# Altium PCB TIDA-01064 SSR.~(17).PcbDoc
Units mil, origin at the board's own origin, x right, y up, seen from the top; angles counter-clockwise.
Board outline 4300 x 2000 mil, 2 copper layers (Top Layer, Bottom Layer), stack 62 mil thick; 74 components, 26 nets, 146 pads, 17 vias.
Unrouted connection lines stored in the file: 26.
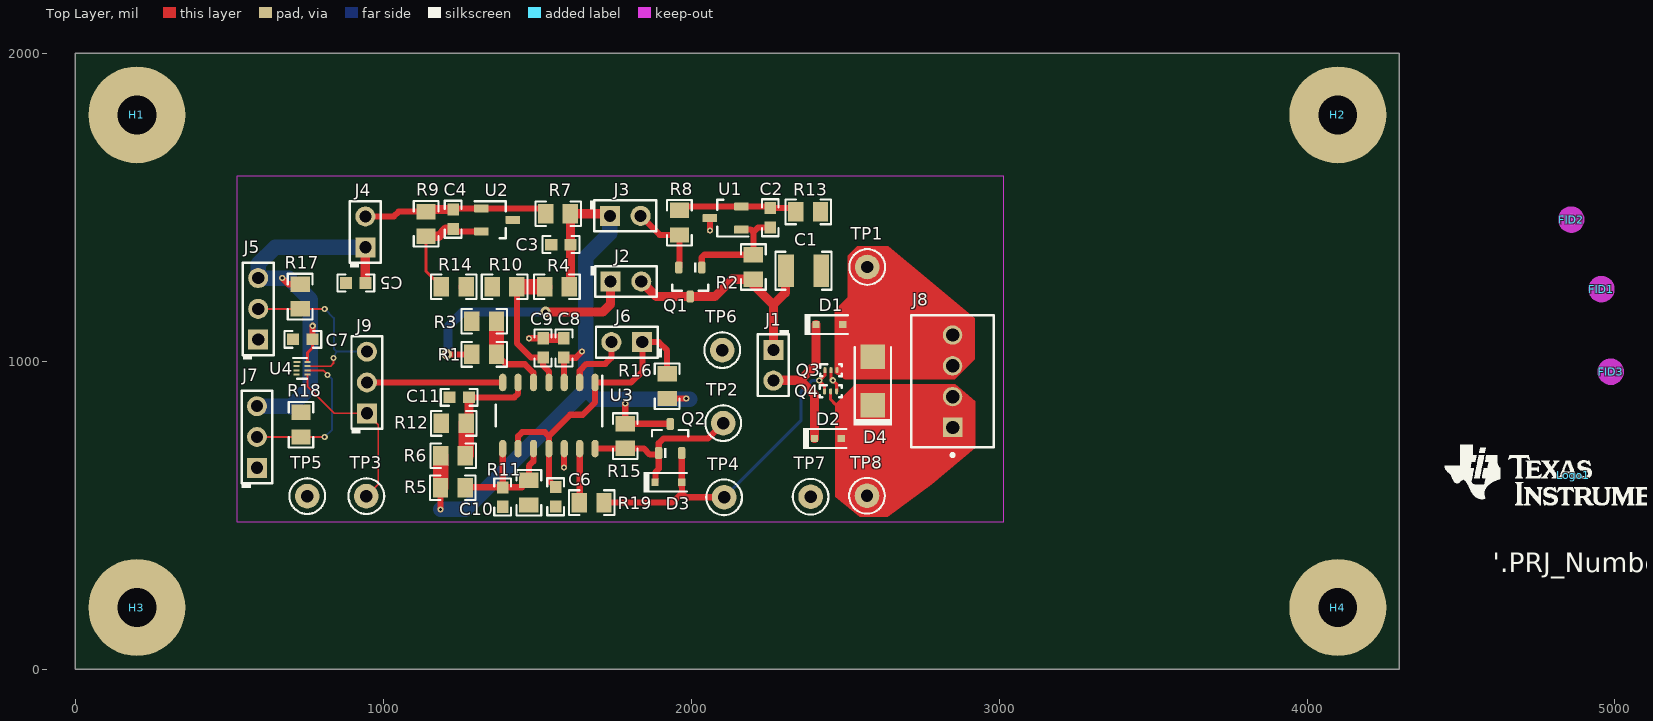
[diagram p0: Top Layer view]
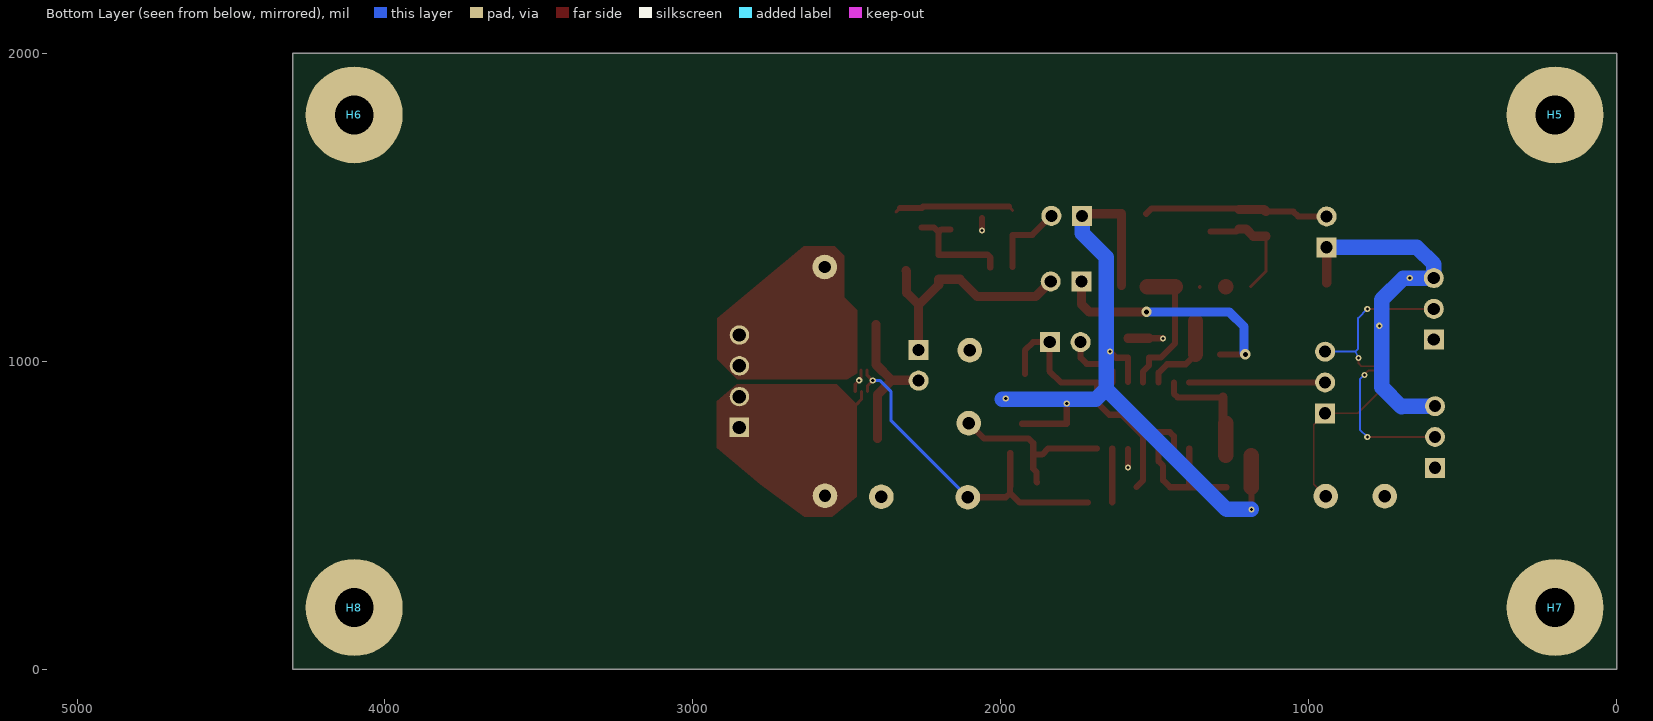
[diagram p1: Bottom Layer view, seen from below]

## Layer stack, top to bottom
Top Solder: solder mask 0.4, Solder Resist, Dk 3.5
Top Layer: signal copper 1.4
Dielectric1: core 59.2, FR-4, Dk 4.8
Bottom Layer: signal copper 1.4
Bottom Solder: solder mask 0.4, Solder Resist, Dk 3.5

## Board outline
0,0 4300,0 4300,2000 0,2000

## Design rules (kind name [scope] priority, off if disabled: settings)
AcuteAngle [All] p1: minimum=4.50000000000000E+0001 checktracksonly=FALSE
AssemblyTestPointUsage [All] p1: valid=2
Clearance Clearance_BoardEdge_MountingHoles [OnCopper and InComponentClass('Mounting Holes') vs IsKeepOut] p1: gap=25
Clearance Clearance_BoardEdge_Poly [OnCopper and InPoly vs IsKeepOut] p2: gap=25
Clearance Clearance_BoardEdge [OnCopper and Not InComponentClass('Logo') and not InComponentClass('FiducialMark') and not InRegion(1000,500,4000,800) and Not IsKeepout vs IsKeepOut] p3: gap=25
Clearance Clearance_Poly [InPolygon] p4: gap=15
Clearance [All] p5: gap=7
ComponentClearance ComponentClearance_Shunt [InComponentClass('Header') vs InComponentClass('Shunt')] p1: gap=0 collisioncheckmode=3 verticalgap=0 showdistances=FALSE
ComponentClearance ComponentClearance_Logo [InComponentClass('Logo')] p2: gap=50 collisioncheckmode=3 verticalgap=10 showdistances=FALSE
ComponentClearance ComponentClearance_ScrewToNut [(HasFootprint('NY PMS 440 0025 PH')) vs (HasFootprint('Keystone_1902C'))] p3: gap=5 collisioncheckmode=3 verticalgap=10 showdistances=FALSE
ComponentClearance ComponentClearance_MountingHoles [InComponentClass('Mounting Holes')] p4: gap=250 collisioncheckmode=3 verticalgap=100000 showdistances=FALSE
ComponentClearance ComponentClearance_SmallPassives [HasFootprint('0201*') or HasFootprint('0402*') or HasFootprint('0508') or HasFootprint('0603*') or HasFootprint('0612') or HasFootprint('0805*') or HasFootprint('0815*') or HasFootprint('0830*') or HasFootprint('1206*') or HasFootprint('1210*') or HasFootprint('1808*') or HasFootprint('1812*') or HasFootprint('1825*') or HasFootprint('2010*') or HasFootprint('2220*') or HasFootprint('2225*') or HasFootprint('2512*') or HasFootprint('2728*') or HasFootprint('3518*') vs HasFootprint('0201*') or HasFootprint('0402*') or HasFootprint('0508') or HasFootprint('0603*') or HasFootprint('0612') or HasFootprint('0805*') or HasFootprint('0815*') or HasFootprint('0830*') or HasFootprint('1206*') or HasFootprint('1210*') or HasFootprint('1808*') or HasFootprint('1812*') or HasFootprint('1825*') or HasFootprint('2010*') or HasFootprint('2220*') or HasFootprint('2225*') or HasFootprint('2512*') or HasFootprint('2728*') or HasFootprint('3518*')] p5: gap=15 collisioncheckmode=3 verticalgap=10 showdistances=FALSE
ComponentClearance ComponentClearance_THtoSMT [IsThruComponent vs IsSMTComponent] p6: gap=50 collisioncheckmode=3 verticalgap=30 showdistances=FALSE
ComponentClearance ComponentClearance_THtoTH [IsThruComponent vs IsThruComponent] p7: gap=50 collisioncheckmode=3 verticalgap=30 showdistances=FALSE
ComponentClearance [All] p8: gap=40 collisioncheckmode=3 verticalgap=10 showdistances=FALSE
DiffPairsRouting [All] p1: maxlimit=100 minlimit=10 mostfreqgap=10 toplayer_minwidth=15 toplayer_maxwidth=15 toplayer_prefwidth=15 bottomlayer_minwidth=15 bottomlayer_maxwidth=15 bottomlayer_prefwidth=15 maxuncoupledlength=1000
FabricationTestPointUsage TestPointUsage [All] p1: valid=2 allowmultiple=FALSE
FabricationTestpoint Testpoint [All] p1: side=3 testpointundercomponent=TRUE minsize=40 maxsize=100 preferedsize=60 minholesize=0 maxholesize=40 preferedholesize=32 testpointgrid=1 allowsidetop=TRUE allowsidebottom=TRUE usegrid=TRUE gridtolerance=0.01
FanoutControl Fanout_LCC [IsLCC] p1: bgadir=Out bgaviamode=Centered fanoutstyle=Auto fanoutdirection=Alternating viagrid=1 // Fanout_LCC (Default Rule)
FanoutControl Fanout_BGA [IsBGA] p2: bgadir=Out bgaviamode=Centered fanoutstyle=Auto fanoutdirection=Alternating viagrid=1 // Fanout_BGA (Default Rule)
FanoutControl Fanout_Default [All] p4: bgadir=Out bgaviamode=Centered fanoutstyle=Auto fanoutdirection=Alternating viagrid=1 // Fanout_Default (Default Rule)
FanoutControl Fanout_Small [(CompPinCount < 5)] p5: bgadir=Out bgaviamode=Centered fanoutstyle=Auto fanoutdirection=OutThenIn viagrid=1 // Fanout_Small (Default Rule)
HoleSize [All] p1: absolutevalues=TRUE maxlimit=251 minlimit=8 maxpercent=80.000 minpercent=20.000
MinimumAnnularRing MinimumAnnularRing_ThermalPadVias [IsVia and InAnyComponent] p1: minimumring=5.91
MinimumAnnularRing [All] p2: minimumring=9
MinimumSolderMaskSliver MinimumSolderMaskSliver_Logo [InComponentClass('Logo') vs InComponentClass('Logo')] p1: minsoldermaskwidth=0.7
MinimumSolderMaskSliver [All] p2: minsoldermaskwidth=3.94
PlaneClearance [All] p1: clearance=15
PlaneConnect [All] p1: planeconnectstyle=Direct reliefexpansion=10 reliefentries=4 reliefconductorwidth=10 reliefairgap=10
PolygonConnect [All] p1: connectstyle=Direct reliefconductorwidth=10 reliefentries=4 polygonreliefangle="90 Angle" airgapwidth=10
RoutingVias ThermalPadVias [IsVia and InAnyComponent] p1: holewidth=7.87 width=19.68 viastyle="Through Hole" minholewidth=7.87 minwidth=19.68 maxholewidth=12.99 maxwidth=23.62
RoutingVias [All] p2: holewidth=16 width=34 viastyle="Through Hole" minholewidth=7.87 minwidth=26 maxholewidth=40 maxwidth=65
SMDToCorner [All] p1: distance=30000
SilkToBoardRegionClearance [Not ((IsComment or IsDesignator) And (Hide <> 'False')) and not InRegion(1000,500,4000,800)] p1:
SilkToSilkClearance [All] p1: silktosilkclearance=0
SilkToSolderMaskClearance SilkscreenOverComponentPads [IsPad] p1: minsilkscreentomaskgap=0 clearancetoexposedcopper=TRUE
SolderMaskExpansion [All] p1: expansion=1.97
Width [All] p1: maxlimit=100 minlimit=6 preferedwidth=10 checkconnectedcopper=TRUE
14 further rules are at their usual default settings.

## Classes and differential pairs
component class "TIDA-01064 SSR_Relay": C1 C2 C3 C4 C6 C7 C8 C9 C10 C11 D1 D2 D3 D4 J1 J2 J3 J4 J5 J6 J7 J8 J9 Q1 Q2 Q3 Q4 R1 R2 R3 R4 R5 R6 R7 R8 R9 R10 R11 R12 R13 R14 R15 R16 R17 R18 R19 TP1 TP2 TP3 TP4 TP5 TP6 TP7 TP8 U1 U2 U3 U4
component class Header: J1 J2 J3 J4 J5 J6 J7 J9
component class "Mounting Holes": H1 H2 H3 H4
component class Logo: Logo1
component class "TIDA-01064 SSR_TID_Hardware": FID1 FID2 FID3 H1 H2 H3 H4 H5 H6 H7 H8 Logo1 ZZ1 ZZ2
component class FiducialMark: FID1 FID2 FID3
component class AssemblyNote: ZZ1 ZZ2

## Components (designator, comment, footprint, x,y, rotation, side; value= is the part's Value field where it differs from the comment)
C1 "C3225X7S2A335M200AB" 1210 2365,1294 r0 top
C2 "GRM1885C1H201JA01D" 0603 2257,1466 r90 top
C3 "GRM188R61E105KA12D" 0603 1577,1379 r180 top
C4 "GRM1885C1H201JA01D" 0603 1227,1461 r270 top
C5 "GRM188R61E105KA12D" 0603 911,1254 r180 top
C6 "GRM188R61E105KA12D" 0603 1560,560 r270 top
C7 "GRM188R71C104KA01D" 0603 739,1071 r0 top
C8 "GRM188R71C104KA01D" 0603 1587,1043 r270 top
C9 "GRM188R71C104KA01D" 0603 1519,1043 r270 top
C10 "GRM188R71C104KA01D" 0603 1388,559 r90 top
C11 "GRM188R71C104KA01D" 0603 1246.68,882.69 r0 top
D1 "1N4448WX-TP" sod-323 2449,1119 r0 top
D2 "1N4448WX-TP" sod-323 2444,749 r0 top
D3 "1N4448WX-TP" sod-323 1926,607 r0 top
D4 "SMAJ40CA" SMA 2590,936 r90 top
FID1 "Fiducial" Fiducial10-20 4956,1234 r0 top
FID2 "Fiducial" Fiducial10-20 4858,1460 r0 top
FID3 "Fiducial" Fiducial10-20 4986,966 r0 top
H1 "NY PMS 440 0025 PH" "NY PMS 440 0025 PH" 200,1800 r0 top locked
H2 "NY PMS 440 0025 PH" "NY PMS 440 0025 PH" 4100,1800 r0 top locked
H3 "NY PMS 440 0025 PH" "NY PMS 440 0025 PH" 200,200 r0 top locked
H4 "NY PMS 440 0025 PH" "NY PMS 440 0025 PH" 4100,200 r0 top locked
H5 "1902C" Keystone_1902C 200,1800 r180 bottom locked
H6 "1902C" Keystone_1902C 4100,1800 r180 bottom locked
H7 "1902C" Keystone_1902C 200,200 r180 bottom locked
H8 "1902C" Keystone_1902C 4100,200 r180 bottom locked
J1 "5-146278-2" TE_5-146278-2 2267,987 r270 top
J2 "5-146278-2" TE_5-146278-2 1788,1259 r0 top
J3 "5-146278-2" TE_5-146278-2 1786,1472 r0 top
J4 "5-146278-2" TE_5-146278-2 942,1420 r90 top
J5 "5-146278-3" TE_5-146278-3 594.02,1170 r90 top
J6 "5-146278-2" TE_5-146278-2 1791,1062 r180 top
J7 "5-146278-3" TE_5-146278-3 590.02,754 r90 top
J8 "282834-4" TEC_282834-4 2849,935 r90 top
J9 "5-146278-3" TE_5-146278-3 947,931 r90 top
Logo1 "Texas Instruments" TI_Stacked_Overlay_Small 4865,630 r0 top
Q1 "MMBTA05LT1G" SOT-23 1997,1257 r270 top
Q2 "MMBT3904LT1G" SOT-23 1932,749 r90 top
Q3 "CSD18541F5" YJK0003A 2454,971 r0 top
Q4 "CSD18541F5" YJK0003A 2453,902 r0 top
R1 "CRCW080510M0FKEA" 0805_HV 1327.71,1022 r0 top
R2 "CRCW0805205KFKEA" 0805_HV 2202,1306 r270 top
R3 "CRCW08053M09FKEA" 0805_HV 1328,1130 r0 top
R4 "CRCW080510M0FKEA" 0805_HV 1564,1242 r0 top
R5 "CRCW080510M0FKEA" 0805_HV 1226,589 r180 top
R6 "RC0805JR-0733ML" 0805_HV 1227,693 r180 top
R7 "CRCW0805100KFKEA" 0805_HV 1568,1479 r0 top
R8 "CRCW08053M74FKEA" 0805_HV 1962,1450 r270 top
R9 "CRCW0805806KFKEA" 0805_HV 1139,1446 r90 top
R10 "CRCW08057M50FKEA" 0805_HV 1394,1242 r0 top
R11 "CRCW08054M32FKEA" 0805_HV 1473,573 r90 top
R12 "CRCW08056M49FKEA" 0805_HV 1229,798 r0 top
R13 "CRCW08051M30FKEA" 0805_HV 2380,1485 r180 top
R14 "CRCW08052M80FKEA" 0805_HV 1229,1242 r180 top
R15 "CRCW080590K9FKEA" 0805_HV 1786,757 r90 top
R16 "CRCW08051M82FKEA" 0805_HV 1922,919 r270 top
R17 "CRCW0805124KFKEA" 0805_HV 730,1210 r90 top
R18 "CRCW0805124KFKEA" 0805_HV 733,794 r90 top
R19 "CRCW08050000Z0EA" 0805_HV 1677,541 r0 top
TP1 "5001" Keystone5001 2572,1306 r0 top
TP2 "5001" Keystone5001 2104,799 r0 top
TP3 "5001" Keystone5001 945.18,561.88 r0 top
TP4 "5001" Keystone5001 2107,558 r0 top
TP5 "5001" Keystone5001 753.18,561.88 r0 top
TP6 "5001" Keystone5001 2101,1036 r0 top
TP7 "5001" Keystone5001 2388,560 r0 top
TP8 "5001" Keystone5001 2571,563 r0 top
U1 "ATL431AIDBZR" DBZ0003A_M 2112,1465 r180 top
U2 "ATL431AIDBZR" DBZ0003A_M 1370,1459 r0 top
U3 "LP339D" D0014A_N 1538,823.68 r270 top
U4 "SN74AUP1G74DQER" DQE0008A 736,977 r0 top
ZZ1 "These assemblies are ESD sensitive, ESD precautions shall be observed." AssemblyNote 185,3829.11 r0 top
ZZ2 "These assemblies must be clean and free from flux and all contaminants. Use of no clean flux is not acceptable." AssemblyNote 185,3740.56 r0 top
ZZ3 "These assemblies must comply with workmanship standards IPC-A-610 Class 2, unless otherwise specified." AssemblyNote 185,3652 r0 top

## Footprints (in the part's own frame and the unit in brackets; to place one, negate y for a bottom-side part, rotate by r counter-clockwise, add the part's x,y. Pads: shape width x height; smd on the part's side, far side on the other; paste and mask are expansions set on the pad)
0603 [mm] "0603 from SM-752 data"
  rect 1x0.95 smd: 1(-0.8,0) 2(0.8,0)
  silkscreen extent -1.52,-0.69 1.52,0.69, body extent -0.87,-0.47 0.87,0.47, height 1
0805_HV [mil] "0805 with 30mil clearance between pads"
  rect 50x63 smd: 1(-40,0) 2(40,0)
  silkscreen extent -74,-40 74,40, body extent -43,-29 43,29, height 57
1210 [mm] "1210 from SM-752 data"
  rect 1.3x2.7 smd: 1(-1.45,0) 2(1.45,0)
  silkscreen extent -2.32,-1.57 2.32,1.57, body extent -1.7,-1.35 1.7,1.35, height 1.35
AssemblyNote [mil] "Assembly Note"
D0014A_N [mm] "SOIC, 14-Leads, Body 8.7x3.9mm, Pitch 1.27mm, IPC Medium Density"
  oval 1.45x0.6 smd: 1(-2.725,3.81) 2(-2.725,2.54) 3(-2.725,1.27) 4(-2.725,0) 5(-2.725,-1.27) 6(-2.725,-2.54) 7(-2.725,-3.81) 8(2.725,-3.81) 9(2.725,-2.54) 10(2.725,-1.27) 11(2.725,0) 12(2.725,1.27) 13(2.725,2.54) 14(2.725,3.81)
  silkscreen extent -3.3,-4.4 0.9,4.4, body extent -3.02,-4.32 3.02,4.32, height 1.6
DBZ0003A_M [mm] "SOT23, 3-Leads, Body 2.9x1.3mm, Pitch 0.95mm, Lead Span 2.4mm, IPC Low Density"
  rrect15% 1.2x0.65 smd: 1(-1.3,0.95) 2(-1.3,-0.95) 3(1.3,0)
  silkscreen extent -1.85,-1.5 0.7,1.53, body extent -1.26,-1.46 1.26,1.46, height 0.98
DQE0008A [mm] "SON, 8-Leads, Body 1.4x1mm, Pitch 0.35mm, TI Recommended"
  rect 0.6x0.16 smd mask+0: 1(-0.4,0.525)
  rect 0.5x0.16 smd mask+0: 2(-0.45,0.175) 3(-0.45,-0.175) 4(-0.45,-0.525) 5(0.45,-0.525) 6(0.45,-0.175) 7(0.45,0.175) 8(0.45,0.525)
  silkscreen extent -0.7,-0.85 0.4,0.85, body extent -0.53,-0.72 0.53,0.73, height 0.41
Fiducial10-20 [mm]
  round 1 smd mask+0.5: 1(0,0)
  Top Layer keep-out circle w1.178: c0,0 r0.5
Keystone5001 [mil] "For Keystone 500x miniature loop terminals"
  round 80 hole 40: 1(0,0)
  silkscreen extent -58,-58 58,58, body extent -49,-49 49,49, height 182
Keystone_1902C [mil] "Hex Standoff, 4-40 threaded, nylon"
  body extent -145,-126 146,126, height 501
"NY PMS 440 0025 PH" [mm] "4-40 nylon screw and mounting hole"
  round 8 hole 3.2: 1(0,0)
  body extent -3.3,-3.3 3.3,3.3, height 2.69
SMA [mm] "Molded Diode, 2-Leads, Body 4.3x2.6mm, IPC Medium Density, based on OnSemi component dimensions and land pattern"
  rect 2x2 smd: 1(-2,0) 2(2,0)
  silkscreen extent -3.66,-1.57 2.79,1.57, body extent -2.6,-1.3 2.6,1.3, height 2.42
sod-323 [mm] "NXP recommended land pattern"
  rect 0.6x0.6 smd paste-0.05: 1(-1.1,0) 2(1.1,0)
  silkscreen extent -2.06,-0.86 1.53,0.86, body extent -1.3,-0.67 1.3,0.68, height 1.1
SOT-23 [mm] "SOT23, 3-Leads, Body 2.9x1.3mm, Pitch 0.95mm, Lead Span 2.5mm, IPC Medium Density"
  rrect50% 1x0.6 smd: 1(-1.2,0.95) 2(-1.2,-0.95) 3(1.2,0)
  silkscreen extent -1.63,-1.5 0.7,1.5, body extent -1.16,-1.45 1.21,1.45, height 1
TE_5-146278-2 [mm] "TE CONNECTIVITY"
  rect 1.65x1.65 hole 1: 1(-1.27,0)
  round 1.65 hole 1: 2(1.27,0)
  silkscreen extent -2.92,-1.27 2.54,1.27, body extent -2.41,-1.17 2.41,1.17, height 8.13
TE_5-146278-3 [mm] "TE CONNECTIVITY"
  rect 1.65x1.65 hole 1: 1(-2.54,0)
  round 1.65 hole 1: 2(0,0) 3(2.54,0)
  silkscreen extent -4.19,-1.27 3.81,1.27, body extent -3.68,-1.17 3.68,1.17, height 8.13
TEC_282834-4 [mm] "TEC"
  rect 1.6x1.6 hole 1.1: 1(-3.81,0)
  round 1.6 hole 1.1: 2(-1.27,0) 3(1.27,0) 4(3.81,0)
  silkscreen extent -6.2,-3.4 5.44,3.4, body extent -5.31,-3.25 5.31,3.25, height 10.02
TI_Stacked_Overlay_Small [mil]
  silkscreen extent -418,-98 418,98
YJK0003A [mm] "SMD, 3-Leads, Body 1.49x0.73mm"
  rrect80% 0.25x0.49 smd paste-0.05 mask-0.05: 1(-0.5,0) 2(0,0) 3(0.5,0)
  silkscreen extent -0.9,-0.5 0.9,0.5, body extent -0.75,-0.37 0.74,0.36, height 0.35

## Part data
C1: "CAP, CERM, 3.3 µF, 100 V, +/- 20%, X7S, 1210"
C2 C4: "CAP, CERM, 200 pF, 50 V, +/- 5%, C0G/NP0, 0603"
C3 C5 C6: "CAP, CERM, 1 µF, 25 V, +/- 10%, X5R, 0603"
C7 C8 C9 C10 C11: "CAP, CERM, 0.1 µF, 16 V, +/- 10%, X7R, 0603"
D1 D2 D3: "Diode, Switching, 75 V, 0.25 A, SOD-323"
D4: "Diode, TVS, Bi, 40 V, 400 W, SMA"
FID1 FID2 FID3: "Fiducial mark.  There is nothing to buy or mount."
H1 H2 H3 H4: "Machine Screw, Round, #4-40 x 1/4, Nylon, Philips panhead"
H5 H6 H7 H8: "Standoff, Hex, 0.5\"L #4-40 Nylon"
J1 J2 J3 J4 J6: "Header, 100mil, 2x1, Tin, TH"
J5 J7 J9: "Header, 100mil, 3x1, Tin, TH"
J8: "Terminal Block, 100mil, 4X1 TH"
Logo1: library part TI_Logo, "Texas Instrument Corporate Signature"
Q1: library part "MMBTA05LT1G, ON Semiconductor", "Transistor, NPN, 60 V, 0.5 A, AEC-Q101, SOT-23"
Q2: library part "MMBT3904LT1G, ON Semiconductor", "Transistor, NPN, 40 V, 0.2 A, SOT-23"
Q3 Q4: "MOSFET, N-CH, 60 V,  A, PICOSTAR-3"
R1 R4 R5: "RES, 10.0 M, 1%, 0.125 W, 0805"
R2: "RES, 205 k, 1%, 0.125 W, 0805"
R3: "RES, 3.09 M, 1%, 0.125 W, 0805"
R6: "RES, 33 M, 5%, 0.125 W, 0805"
R7: "RES, 100 k, 1%, 0.125 W, 0805"
R8: "RES, 3.74 M, 1%, 0.125 W, 0805"
R9: "RES, 806 k, 1%, 0.125 W, 0805"
R10: "RES, 7.50 M, 1%, 0.125 W, 0805"
R11: "RES, 4.32 M, 1%, 0.125 W, 0805"
R12: "RES, 6.49 M, 1%, 0.125 W, 0805"
R13: "RES, 1.30 M, 1%, 0.125 W, 0805"
R14: "RES, 2.80 M, 1%, 0.125 W, 0805"
R15: "RES, 90.9 k, 1%, 0.125 W, 0805"
R16: "RES, 1.82 M, 1%, 0.125 W, 0805"
R17 R18: "RES, 124 k, 1%, 0.125 W, 0805"
R19: "RES, 0, 5%, 0.125 W, 0805"
TP1 TP2 TP3 TP4 TP5 TP6 TP7 TP8: "Test Point, Miniature, Black, TH"
U1 U2: "2.5V Low Iq Adjustable Precision Shunt Regulator, DBZ0003A"
U3: "Quad, Low-Power, General Purpose Differential Comparator, D0014A"
U4: "LOW-POWER SINGLE POSITIVE-EDGE-TRIGGERED D-TYPE FLIP-FLOP WITH CLEAR AND PRESET, DQE0008A"
ZZ1 ZZ2 ZZ3: library part AssemblyNote

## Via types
v1: diameter 20, hole 10, Top Layer to Bottom Layer, 15 vias
v2: diameter 34, hole 16, Top Layer to Bottom Layer, 2 vias

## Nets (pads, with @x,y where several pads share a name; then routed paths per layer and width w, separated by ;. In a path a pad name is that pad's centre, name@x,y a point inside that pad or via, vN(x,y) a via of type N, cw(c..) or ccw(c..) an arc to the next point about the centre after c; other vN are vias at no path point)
3.3V: C5.1 C7.2 J4.1 J5.3 J7.3 R17.2 R18.2 U4.8 | length 1404.1
  Top Layer w10: U4.8@753.72,1000.04 753.72,1026.52 770.5,1043.3 C7.2
  Top Layer w20: v1(672,1270) 692,1250 R17.2 ; C7.2 770.5,1114.5 v1(771,1115)
  Top Layer w30: J4.1 942,1254.5 C5.1
  Bottom Layer w50: J7.3@591.02,853 J7.3 697,854 699,852 763,916 763,1200 693,1270 v1(672,1270) J5.3 594.02,1314.98 649.04,1370 J4.1
10V: C3.1 C8.2 J3.1 Q2.3 R4.2 R5.2 R6.2 R7.2 R15.2 R16.2 U3.3 | length 2545.4
  Top Layer w10: R5.2 R5.2@1187,590 ; U3.3@1587,931.97 U3.3 ; R4.2 R4.2@1608.5,1246.5 ; C3.1@1608,1379.5 C3.1 ; J3.1@1729,1479 J3.1
  Top Layer w20: v1(1186,519) R5.2 ; U3.3@1587,931.97 C8.2 1625.5,1011.5 v1(1646,1032) ; v1(1786,863) R15.2 Q2.3@1931.24,797 ; R16.2 v1(1984,879)
  Top Layer w30: C3.1@1608,1379.5 R7.2 J3.1@1729,1479 ; R4.2@1608.5,1246.5 C3.1
  Top Layer w50: R5.2@1187,590 R6.2
  Bottom Layer w50: v1(1186,519) 1267,519 1658,910 ; J3.1 1736,1416 1658,1338 1658,910 ; 1995,876 1692,876 1658,910
GND: C1.2 C3.2 C5.2 C6.2 C7.1 C8.1 C9.1 C10.1 C11.1 J5.1 J7.1 Q3.2 Q4.3 R3.1 R10.1 R11.1 R12.1 R13.1 R14.1 TP5.1 TP6.1 TP7.1 U1.3 U2.3 U3.12 U4.1 U4.2 U4.4 | length 296.8
  Top Layer w10: R10.1@1354,1239 R10.1 ; v1(1587,655) v1@1588,656 ; Q3.2 2454,944 v1(2460,938) 2472.69,925.31 Q4.3
  Top Layer w20: v1(1473,1074) 1473.5,1074.5 C9.1 ; v1(1587,655) U3.12@1587,715.4 ; U1.3 2060.82,1424.18 v1(2061,1424)
  Top Layer w30: C9.1 C8.1
HV1: D1.2 D4.2 J8.3 J8.4 Q3.3 TP1.1 | length 0.4
  Top Layer w20: D4.2@2589.74,1015 D4.2
HV2: D2.2 D4.1 J8.1 J8.2 Q4.2 TP8.1 | length 49.2
  Top Layer w10: Q4.2 2453,875.75 2468,860.75
  Top Layer w20: D4.1@2588.74,856 D4.1
NetC1_1: C1.1 J1.1 J2.2 Q1.3 R2.2 | length 791.6
  Top Layer w30: J2.2 1887.24,1209.76 Q1.3 2076.76,1209.76 2133,1266 R2.2 2202,1248 2267,1183 ; J1.1 2267,1183 ; C1.1 2306,1292.09 2306,1222 2267,1183
NetC2_1: C2.1 Q1.1 R2.1 U1.1 | length 381.8
  Top Layer w10: 2034,1337 2034.4,1336.6 ; 2192.6,1427.6 2193,1428
  Top Layer w20: 2034,1337 2043,1346 R2.1 2202,1419 ; Q1.1 2034.4,1336.6 ; U1.1 2192.6,1427.6 ; 2193,1428 2202,1419 ; C2.1 2217.5,1434.5 2202,1419
NetC2_2: C2.2 R8.1 R13.2 U1.2 | length 390.3
  Top Layer w10: R8.1 R8.1@1974.4,1502.4 ; C2.2@2252.09,1502.4 C2.2 ; R13.2@2327.5,1497.5 R13.2
  Top Layer w20: R8.1@1974.4,1502.4 U1.2 C2.2@2252.09,1502.4 ; C2.2 R13.2@2327.5,1497.5
NetC4_1: C4.1 J4.2 R7.1 R9.2 U2.1 | length 609.5
  Top Layer w10: U2.1@1314.91,1492.5 U2.1
  Top Layer w20: J4.2 1034,1470 1050,1486 R9.2 ; C4.1 1230.5,1496 U2.1 1510.6,1496.4 R7.1
  Top Layer w30: R9.2 1145.5,1492.5 C4.1
NetC4_2: C4.2 R9.1 R14.2 U2.2 | length 377.5
  Top Layer w10: R9.1 1139,1292 R14.2
  Top Layer w20: C4.2 1234.91,1421.6 U2.2
  Top Layer w30: R9.1 1180,1406 1203.5,1429.5 C4.2
NetC6_1: C6.1 J6.1 R16.1 U3.1 U3.9 U3.11 | length 1018
  Top Layer w10: J6.1 J6.1@1842,1061
  Top Layer w20: U3.9 1438,757 1451,770 1525,770 1538,757 ; C6.1 1538,613.5 U3.11 1538,757 ; J6.1 1895,1062 1922,1035 R16.1 ; J6.1@1842,1061 1842,968 1804.97,930.97 U3.1 1688,866 1648,826 1607,826 1538,757
NetD1_1: D1.1 D2.1 J1.2 | length 498.2
  Top Layer w30: J1.2 2268,938 2354,938 ; D2.1 2400.69,891.31 2354,938 ; D1.1 2405.69,1053.75 2405.39,1053.45 2405.39,989.39 2354,938
NetD3_1: D3.1 Q2.1 R15.1 TP2.1 U3.14 | length 583.1
  Top Layer w10: R15.1@1785.4,716.4 R15.1
  Top Layer w20: U3.14 R15.1@1785.4,716.4 ; R15.1 1846,717 1866,697 Q2.1@1894.35,697 ; D3.1 1884,608.31 1884,640 1894.6,650.6 1894.6,696.76 Q2.1@1894.35,697 ; TP2.1 2054,749 1910,749 1895,734 1895,697.65 Q2.1@1894.35,697
NetD3_2: D3.2 Q2.2 Q3.1 Q4.1 R19.2 TP4.1 | length 1143.8
  Top Layer w10: Q4.1 2433.32,919.68 v1(2416,937) 2417,937 2434.32,954.32 Q3.1
  Top Layer w20: R19.2 1939,541 1970,572 ; Q2.2 1969.4,607.09 D3.2 1970,572 ; TP4.1 1984,558 1970,572
  Bottom Layer w10: TP4.1 2357,808 2357,902 2392,937 v1(2416,937)
NetJ2_1: J2.1 R1.1 | length 805.6
  Top Layer w20: v2(1206,1022) R1.1
  Top Layer w30: v2(1527,1160) 1713,1160 1738,1185 J2.1
  Bottom Layer w30: v2(1206,1022) 1210,1026 1210,1112 1258,1160 v2(1527,1160)
NetJ3_2: J3.2 Q1.2 R8.2 | length 258.4
  Top Layer w10: Q1.2 Q1.2@1962,1306.65
  Top Layer w20: J3.2 1898,1410 R8.2 Q1.2@1962,1306.65
NetJ6_2: J6.2 U3.2 | length 209.4
  Top Layer w20: U3.2 1638,969 1660,991 1721,991 1741,1011 J6.2
NetJ9_1: J9.1 TP3.1 U4.5 | length 568
  Top Layer w6: U4.5 753.72,918.28 841,831 J9.1 984,794 984,600.71 TP3.1
NetJ9_2: J9.2 U3.7 | length 441
  Top Layer w20: J9.2 U3.7
NetR19_1: R19.1 U3.13 | length 177.2
  Top Layer w10: R19.1 R19.1@1638,542 ; U3.13@1637,715.4 U3.13
  Top Layer w20: R19.1@1638,542 U3.13
OFF#: J7.2 R18.1 U4.6 | length 509.3
  Top Layer w6: J7.2 R18.1 v1(810,754) ; U4.6 804.89,970.11 v1(819.5,955.5)
  Bottom Layer w6: v1(810,754) 834,778 834,941 v1(819.5,955.5)
ON#: J5.2 J9.3 R17.1 U4.7 | length 598
  Top Layer w6: J5.2 R17.1 v1(810,1170) ; U4.7 828.89,983.89 838,993 v1(838,1011)
  Bottom Layer w6: v1(810,1170) 840,1140 840,1040 849,1031 ; v1(838,1011) 849,1031 ; J9.3 849,1031
VREF1: C9.2 R4.1 R10.2 U3.4 | length 466.7
  Top Layer w10: C9.2@1518.5,1012 C9.2
  Top Layer w20: R10.2 1434,1058 1480,1012 C9.2@1518.5,1012 ; C9.2 1519,986 1538,967 U3.4
  Top Layer w50: R10.2 R4.1
VREF2: C10.2 R5.1 R11.2 U3.8 U3.10 | length 454.5
  Top Layer w10: R5.1 R5.1@1267.5,590.5 ; U3.8 U3.8@1389.45,714.95
  Top Layer w20: R5.1@1267.5,590.5 C10.2 ; U3.8 C10.2 ; U3.10 1488,675 1473,660 R11.2 1450.5,590.5 C10.2
VREF3: C11.2 R6.1 R12.2 U3.6 | length 395.2
  Top Layer w10: R6.1 R6.1@1269,695 ; R12.2 R12.2@1278.18,807.18
  Top Layer w20: C11.2 1425.69,882.69 1438,895 U3.6
  Top Layer w30: R12.2@1278.18,807.18 C11.2
  Top Layer w50: R6.1@1269,695 R12.2
VUVLO: R1.2 R3.2 U3.5 | length 284.7
  Top Layer w10: R3.2@1367.71,1129.71 R3.2 ; 1487.26,962.74 1488,962.74
  Top Layer w20: R1.2 1399.71,990 1460,990 1487.26,962.74 ; U3.5 1488,962.74
  Top Layer w50: R1.2 R3.2@1367.71,1129.71
pads on no net: FID1.1 FID2.1 FID3.1 H1.1 H2.1 H3.1 H4.1 U4.3

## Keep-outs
Top Layer:
  rectangle net GND: 525,478 3015,1600
Keep-Out Layer:
  text ".Layer_Name" at 577,-858.49 h60

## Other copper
Top Layer:
  region net HV1: 2546,942 2499,942 2466.5,961 2466.5,1007 2466.5,1166 2508.75,1208.25 2508.75,1343 2539.25,1373.5 2640,1373.5 2775,1261 2921.5,1138.92 2921.5,1007 2856.5,942 2697,942
  region net HV2: 2547.5,494.25 2468,559.25 2468,860.75 2533,925.75 2858,925.75 2923,869.75 2923,718.75 2781,601 2639,494.25
  text ".Layer_Name" at 577,-858.49 h60
Bottom Layer:
  text ".Layer_Name" at 577,-858.49 h60

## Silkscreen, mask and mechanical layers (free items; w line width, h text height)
Top Overlay:
  text "'.PRJ_Number' .PCB_Rev" at 4603,294 h108.27
  text ".Layer_Name" at 577,-858.49 h60
Bottom Overlay:
  text ".Layer_Name" at 577,-858.49 h60
Top Paste:
  text ".Layer_Name" at 577,-858.49 h60
Bottom Paste:
  text ".Layer_Name" at 577,-858.49 h60
Top Solder:
  text ".Layer_Name" at 577,-858.49 h60
  text ".Layer_Name" at 577,-858.49 h60
Bottom Solder:
  text ".Layer_Name" at 577,-858.49 h60
Drill Guide:
  text ".Layer_Name" at 577,-858.49 h60
M1 Board Outline:
  the board outline again, w10
  text ".Layer_Name" at 577,-858.49 h60
M2 Board Dimensions:
  rectangle: 0,-275 125,-150
  rectangle: 125,-400 500,-275
  lines w7: 0,-275 1000,-275 ; 125,-400 125,-150 ; 250,-400 250,-150 ; 500,-400 500,-150 ; 750,-400 750,-150 ; 0,-400 1000,-400 1000,-150 0,-150 0,-400
  text ".Layer_Name" at 577,-858.49 h60
M3 3D STEP Top:
  text ".Layer_Name" at 577,-858.49 h60
M4 3D STEP Bottom:
  text ".Layer_Name" at 577,-858.49 h60
M5 Assembly Top:
  lines w10: -292,-930.17 6308,-930.17 ; -292,-726.83 6310,-726.83 ; -292,-523.5 -292,-1133.5 3713,-1133.5 6310,-1133.5 6310,-523.5 -291.5,-523.5 -291.5,-1133.5 1284,-1133.5 ; 2173,-1133.5 2173,-523.5 ; 3440,-726.83 3440,-523.5 ; 4280,-726.83 4280,-523.5 ; 4902,-1140 4902,-937.17
  text "COMPONENTS MARKED 'DNP' SHOULD NOT BE POPULATED." at 1153.5,-318.5 h60
  text "ASSEMBLY VARIANT:" at 1153,-434 h60
  text ".VariantName" at 2189,-434 h60
  text "PCB VIEWED FROM TOP SIDE" at -228.5,-655.67 h60
  text "BOARD #:" at 2248,-655.67 h60
  text ".PRJ_Number" at 2793.5,-655.67 h60
  text "REV:" at 3638,-655.67 h60
  text ".PCB_Rev" at 3929.5,-655.67 h60
  text "SVN REV:" at 4476,-655.67 h60
  text ".VersionControl_RevNumber" at 4982,-655.67 h60
  text "TID #:" at 2248,-859 h60
  text ".TID" at 2793.5,-859 h60
  text "PLOT NAME =" at -228.5,-1064.34 h60
  text ".plot_File_Name" at 577,-1064.34 h60
  text "GENERATED    :" at 2250,-1064.34 h60
  text ".Print_Date" at 3119.5,-1064.34 h60
  text ".Print_Time" at 3848.5,-1064.34 h60
  text "TEXAS INSTRUMENTS" at 5113,-1064.34 h60
M6 Assembly Bottom:
  lines w10: -292.5,-727.33 6309.5,-727.33 ; -290.5,-930.67 6309.5,-930.67 ; 1115.5,-1140.5 1115.5,-937.67 ; 1737.5,-727.33 1737.5,-524 ; 2577.5,-727.33 2577.5,-524 ; 3844.5,-1134 3844.5,-524 ; 4733.5,-1134 6309,-1134 6309,-524 -292.5,-524 -292.5,-1134 2304.5,-1134 6309.5,-1134 6309.5,-524
  text "COMPONENTS MARKED 'DNP' SHOULD NOT BE POPULATED." at 6102,-318 h60
  text ".VariantName" at 5058,-434 h60
  text "ASSEMBLY VARIANT:" at 6097,-434 h60
  text ".VersionControl_RevNumber" at 1035.5,-656.17 h60
  text "SVN REV:" at 1541.5,-656.17 h60
  text ".PCB_Rev" at 2088,-656.17 h60
  text "REV:" at 2379.5,-656.17 h60
  text ".PRJ_Number" at 3224,-656.17 h60
  text "BOARD #:" at 3769.5,-656.17 h60
  text "PCB VIEWED FROM BOTTOM SIDE" at 6246,-656.17 h60
  text ".TID" at 3224,-859.5 h60
  text "TID #:" at 3769.5,-859.5 h60
  text "TEXAS INSTRUMENTS" at 904.5,-1064.84 h60
  text ".Print_Time" at 2169,-1064.84 h60
  text ".Print_Date" at 2898,-1064.84 h60
  text "GENERATED    :" at 3767.5,-1064.84 h60
  text ".plot_File_Name" at 5440.5,-1064.84 h60
  text "PLOT NAME =" at 6246,-1064.84 h60
M9 Title Sheet:
  drawing of 57 lines, arcs and shapes, not listed
  text "1" at 739.84,8036.5 h70
  text "2" at 3235.5,8036.5 h70
  text "3" at 5724.84,8036.5 h70
  text "4" at 8231.51,8036.5 h70
  text "5" at 10730.5,8036.5 h70
  text "6" at 13235.5,8036.5 h70
  text "A" at -416.5,6893.5 h70
  text "A" at 14383.5,6893.5 h70
  text "B" at -416.5,4513.5 h70
  text "B" at 14383.5,4513.5 h70
  text "C" at -416.5,2138.5 h70
  text "C" at 14383.5,2138.5 h70
  text "PROJECT TITLE:" at 11343.5,277.5 h45
  text ".PRJ_Title" at 11393.5,144.17 h70
  text "DESIGNED FOR:" at 11343.5,-23.5 h45
  text ".PRJ_Customer" at 11393.5,-163.5 h70
  text "D" at -416.5,-231.5 h70
  text "D" at 14383.5,-231.5 h70
  text "FILE NAME:" at 11343.5,-323.5 h45
  text ".PCB_File_Name_No_Path" at 11393.5,-443.5 h70
  text "Texas Instruments (TI) and/or its licensors do not warrant the accuracy or completeness of this specification" at 6374,-605.34 h45
  text "ENGINEER:" at 11343.5,-613.5 h45
  text "LAYOUT BY:" at 12848.5,-613.5 h45
  text "or any information contained therein. TI and/or its licensors do not warrant that this design will meet" at 6329.01,-718 h45
  text ".PRJ_Engineer" at 11393.5,-768.49 h70
  text ".PCB_Layout" at 12899,-768.49 h70
  text "the specifications, will be suitable for your application or fit for any particular purpose, or will operate in" at 6329.01,-830.67 h45
  text ".Layer_Name" at 577,-858.49 h60
  text "ALTIUM DESIGNER VERSION:" at 12848.5,-923.5 h45
  text "an implementation. TI and/or its licensors do not warrant that the design is production worthy. You should" at 6329.01,-943.33 h45
  text "completely validate and test your design implementation to confirm the system functionality for your application." at 6374,-1056 h45
  text ".print_Scale" at 11393.5,-1056.83 h70
  text ".Application_BuildNumber" at 12899,-1056.83 h70
  text "1" at 739.84,-1263.5 h70
  text "2" at 3235.5,-1263.5 h70
  text "3" at 5724.84,-1263.5 h70
  text "4" at 8231.51,-1263.5 h70
  text "5" at 10730.5,-1263.5 h70
  text "6" at 13235.5,-1263.5 h70
M10 Fab Notes:
  drawing of 173 lines, arcs and shapes, not listed
  text "DESIGN INFORMATION" at 12378.02,6201 h60
  text "MIN. TRACK WIDTH:" at 11733.46,6021 h60
  text "8" at 12829.7,6021 h60
  text "MIL" at 12984.46,6021 h60
  text "MIN. CLEARANCE:" at 11733.46,5889 h60
  text "0.2" at 12769.7,5889 h60
  text "mm" at 12984.46,5889 h60
  text "MIN. VIA PAD SIZE:" at 11733.46,5757 h60
  text "24" at 12799.71,5757 h60
  text "MIL" at 12984.46,5757 h60
  text "0.05mm (2MIL)" at 12428.46,5615.29 h60
  text "MINIMUM ANNULAR RING" at 11404.23,5611 h60
  text "EXTERNAL" at 13136.46,5611 h60
  text "PER" at 11604.23,5493 h60
  text "IPC-D-275 CLASS 2 LEVEL C" at 11824.23,5493 h60
  text "MIL, HOLES" at 13312.46,5380.71 h60
  text "+/-" at 12920,5380 h60
  text "+/-" at 13774,5380 h60
  text "REGISTRATION TOLERANCES:" at 11404.23,5375 h60
  text "METAL" at 12604,5375 h60
  text "5" at 13180.2,5375 h60
  text "3" at 14013.2,5375 h60
  text "MIL" at 14129.46,5375 h60
  text "+/-" at 13774,5262 h60
  text "HOLE SIZE TOLERANCE (UNLESS OTHERWISE SPECIFIED):" at 11404.23,5257 h60
  text "3" at 14013.2,5257 h60
  text "MIL" at 14129.46,5257 h60
  text "MATERIAL:" at 11329.46,5047.54 h60
  text "FR-4 High Tg" at 12315.9,4907.21 h60
  text "FR-408" at 11750.46,4898.64 h60
  text "OTHER" at 13238.46,4898.64 h60
  text "X" at 12161,4895 h60
  text "62 MIL (1.6mm) +/-10%" at 12070.56,4735.92 h60
  text "THICKNESS:" at 11404.23,4731.64 h60
  text "X" at 11942.4,4731.64 h60
  text "OTHER" at 13355.46,4731.64 h60
  text "TOLERANCE:" at 11404.23,4573.64 h60
  text "X" at 12243.53,4573.64 h60
  text "ANSI IPC-6012 TYPE 3 CLASS 2" at 12430.48,4573.64 h60
  text "OTHER +/-" at 12430.46,4417.64 h60
  text "BOW & TWIST:" at 11404.23,4260.64 h60
  text "X" at 12243.53,4260.64 h60
  text "ANSI IPC-6012 TYPE 3 CLASS 2" at 12430.48,4260.64 h60
  text "OTHER +/-" at 12430.46,4102.13 h60
  text "DRILLING:" at 11329.46,3963.64 h60
  text "REFERENCE:" at 11404.23,3846.64 h60
  text "X" at 12052.46,3846.64 h60
  text "AS SHOWN" at 12239.46,3846.64 h60
  text "X" at 12953.46,3846.64 h60
  text "NC_DRILL FILES" at 13090.46,3846.64 h60
  text "PTH COPPER THICKNESS:" at 11404.23,3688.64 h60
  text "X" at 12534.46,3688.64 h60
  text "20-30 um" at 12671.46,3688.64 h60
  text "OTHER" at 13388.46,3688.64 h60
  text "BOARD FINISH:" at 11329.46,3529.64 h60
  text "SILKSCREEN:" at 11484.68,3411.64 h60
  text "X" at 12433.46,3411.64 h60
  text "TOP" at 12559.46,3411.64 h60
  text "X" at 12943.46,3411.64 h60
  text "BOTTOM" at 13070.46,3411.64 h60
  text "SILKSCREEN COLOR:" at 11484.68,3244.64 h60
  text "X" at 12432.42,3244.64 h60
  text "WHITE" at 12559.46,3244.64 h60
  text "OTHER" at 13070.46,3244.64 h60
  text "X" at 12563.42,3085.44 h60
  text "GREEN" at 12690.46,3085.44 h60
  text "OTHER" at 13308.46,3085.44 h60
  text "SOLDER RESIST COLOR:" at 11484.68,3074.64 h60
  text "X" at 12563.42,2915.44 h60
  text "MATTE" at 12690.46,2915.44 h60
  text "SEMI-GLOSS" at 13308,2914.8 h60
  text "IMMERSION GOLD (ENIG)" at 12390.46,2726.92 h60
  text "ENEPIG" at 13728,2723.64 h60
  text "SURFACE FINISH:" at 11329.46,2722.64 h60
  text "X" at 12203.51,2722.64 h60
  text "IMM. TIN/SILVER OR EQUIV" at 11659,2565.64 h60
  text "OTHER" at 13090.46,2565.64 h60
  text "ARRAY/PANEL:" at 11329.46,2386.64 h60
  text "CUT AND TRIM PER M1 BOARD OUTLINE" at 12390.46,2382.35 h60
  text "N.C. ROUTE" at 12390.46,2230.64 h60
  text "X" at 13069.46,2230.64 h60
  text "V. SCORE" at 13256.46,2230.64 h60
  text "CERTIFICATION:" at 11329.46,2093.64 h60
  text "MATERIALS AND WORKMANSHIP FOR ALL PCBS" at 12054.46,2093.64 h60
  text "TO MEET OR EXCEED THE REQUIREMENTS OF:" at 12054.46,1995.64 h60
  text "X" at 11680.96,1859.13 h60
  text "ANSI IPC-A-600F CLASS ->" at 11819.96,1859.13 h60
  text "X" at 13459.02,1859.13 h60
  text "2" at 13577.96,1859.14 h60
  text "1" at 13262.96,1857.64 h60
  text "3" at 13931.96,1857.64 h60
  text "X" at 12495.02,1699.64 h60
  text "RoHS" at 12631.96,1699.64 h60
  text "OTHER" at 13276.36,1699.64 h60
  text "PER ORDER" at 13673.42,1699.64 h60
  text "ALL BOARDS MUST MEET OR EXCEED UL94-V0 REQUIREMENTS." at 11357,1534 h60
  text "PCB MUST BEAR THE UL94V-0 UL REGISTERED MATERIAL ID NUMBER" at 11357,1414 h60
  text "ADDITIONAL REQUIREMENTS:" at 11329.46,1240.64 h60
  text "MICROSECTION:" at 11404.23,1125.64 h60
  text "YES" at 12309.96,1125.64 h60
  text "REQUIRED" at 13171.46,969.49 h60
  text "BARE BOARD ELEC. TEST:" at 11404.23,966.64 h60
  text "NONE" at 12709.96,966.64 h60
  text "X" at 13044.46,966.64 h60
  text "PER ORDER" at 13763.46,966.64 h60
  text ".Layer_Name" at 577,-858.49 h60
M11 Gerber Information:
  lines w10: -292,-930.17 6308,-930.17 ; -292,-726.83 6310,-726.83 ; -292,-523.5 -292,-1133.5 3713,-1133.5 6310,-1133.5 6310,-523.5 -291.5,-523.5 -291.5,-1133.5 1284,-1133.5 ; 2173,-1133.5 2173,-523.5 ; 3440,-726.83 3440,-523.5 ; 4280,-726.83 4280,-523.5 ; 4902,-1140 4902,-937.17
  text "ALL ARTWORK VIEWED FROM TOP SIDE" at -228.5,-655.67 h60
  text "BOARD #:" at 2248,-655.67 h60
  text ".PRJ_Number" at 2793.5,-655.67 h60
  text "REV:" at 3638,-655.67 h60
  text ".PCB_Rev" at 3929.5,-655.67 h60
  text "SVN REV:" at 4476,-655.67 h60
  text ".VersionControl_RevNumber" at 4982,-655.67 h60
  text "LAYER NAME =" at -228.5,-858.49 h60
  text "TID #:" at 2248,-859 h60
  text ".TID" at 2793.5,-859 h60
  text "PLOT NAME =" at -228.5,-1064.34 h60
  text ".plot_File_Name" at 577,-1064.34 h60
  text "GENERATED    :" at 2250,-1064.34 h60
  text ".Print_Date" at 3119.5,-1064.34 h60
  text ".Print_Time" at 3848.5,-1064.34 h60
  text "TEXAS INSTRUMENTS" at 5113,-1064.34 h60
M12 Stackup:
  drawing of 191 lines, arcs and shapes, not listed
  text "Layer" at 9790.34,7830 h60
  text "Name" at 10200.26,7830 h60
  text "Material" at 11130,7830 h60
  text "Thickness" at 11989.77,7830 h60
  text "Constant" at 12639.6,7830 h60
  text "Board Layer Stack" at 13209.46,7830 h60
  text "1" at 9790.34,7710 h60
  text "Top Overlay" at 10200.26,7710 h60
  text "2" at 9790.34,7590 h60
  text "Top Solder" at 10200.26,7590 h60
  text "Solder Resist" at 11130,7590 h60
  text "0.40mil" at 11989.77,7590 h60
  text "3.5" at 12639.6,7590 h60
  text "3" at 9790.34,7470 h60
  text "Top Layer" at 10200.26,7470 h60
  text "Copper" at 11130,7470 h60
  text "1.40mil" at 11989.77,7470 h60
  text "4" at 9790.34,7350 h60
  text "Dielectric1" at 10200.26,7350 h60
  text "FR-4" at 11130,7350 h60
  text "59.20mil" at 11989.77,7350 h60
  text "4.8" at 12639.6,7350 h60
  text "5" at 9790.34,7230 h60
  text "Bottom Layer" at 10200.26,7230 h60
  text "Copper" at 11130,7230 h60
  text "1.40mil" at 11989.77,7230 h60
  text "6" at 9790.34,7110 h60
  text "Bottom Solder" at 10200.26,7110 h60
  text "Solder Resist" at 11130,7110 h60
  text "0.40mil" at 11989.77,7110 h60
  text "3.5" at 12639.6,7110 h60
  text "7" at 9790.34,6990 h60
  text "Bottom Overlay" at 10200.26,6990 h60
  text ".Layer_Name" at 577,-858.49 h60
M13 Component Bodies Top:
  text ".Layer_Name" at 577,-858.49 h60
M14 Component Bodies Bottom:
  text ".Layer_Name" at 577,-858.49 h60
M15 Courtyards Top:
  text ".Layer_Name" at 577,-858.49 h60
M16 Courtyards Bottom:
  text ".Layer_Name" at 577,-858.49 h60
Drill Drawing:
  circle w10: c5363.72,2644.68 r27.63
  lines w10: 5336.09,2755.19 5349.9,2755.19 5363.72,2741.38 5377.53,2755.19 5391.34,2755.19 5377.53,2769 5391.34,2782.82 5377.53,2782.82 5363.72,2796.63 5349.9,2782.82 5336.09,2782.82 5349.9,2769 5336.09,2755.19 ; 5336.09,2920.95 5391.34,2920.95 5363.72,2865.7 5336.09,2920.95 ; 5336.09,2990.02 5391.34,2990.02 5391.34,3045.27 5336.09,3045.27 5336.09,2990.02 ; 5336.09,3114.34 5363.72,3128.15 5391.34,3114.34 5377.53,3141.96 5391.34,3169.59 5363.72,3155.78 5336.09,3169.59 5349.9,3141.96 5336.09,3114.34 ; 5336.09,3252.47 5349.9,3252.47 5349.9,3238.66 5377.53,3238.66 5377.53,3252.47 5391.34,3252.47 5391.34,3280.1 5377.53,3280.1 5377.53,3293.91 5349.9,3293.91 5349.9,3280.1 5336.09,3280.1 5336.09,3252.47
  lines w12: 5286,2579.76 8517.49,2579.76 ; 5286,3325.68 8517.49,3325.68 ; 5623.86,2455.44 5623.86,3450 ; 5955.86,2455.44 5955.86,3450 ; 6592.43,2455.44 6592.43,3450 ; 6851.57,2455.44 6851.57,3450 ; 7226.72,2455.44 7226.72,3450 ; 7951.05,2455.44 7951.05,3450 ; 5286,2455.44 8517.49,2455.44 8517.49,3450 5286,3450 5286,2455.44
  text "Symbol" at 5360.59,3362.98 h72
  text "Quantity" at 5661.16,3362.98 h72
  text "Finished Hole Size" at 5993.16,3362.98 h72
  text "Plated" at 6629.72,3362.98 h72
  text "Hole Type" at 6888.86,3362.98 h72
  text "Drill Layer Pair" at 7264.02,3362.98 h72
  text "Hole Tolerance" at 7988.35,3362.98 h72
  text "15" at 5661.16,3238.66 h60
  text "10.00mil (0.254mm)" at 5993.16,3238.66 h60
  text "PTH" at 6629.72,3238.66 h60
  text "Round" at 6888.86,3238.66 h60
  text "Top Layer - Bottom Layer" at 7264.02,3238.66 h60
  text "2" at 5661.16,3114.34 h60
  text "16.00mil (0.406mm)" at 5993.16,3114.34 h60
  text "PTH" at 6629.72,3114.34 h60
  text "Round" at 6888.86,3114.34 h60
  text "Top Layer - Bottom Layer" at 7264.02,3114.34 h60
  text "19" at 5661.16,2990.02 h60
  text "39.37mil (1.000mm)" at 5993.16,2990.02 h60
  text "PTH" at 6629.72,2990.02 h60
  text "Round" at 6888.86,2990.02 h60
  text "Top Layer - Bottom Layer" at 7264.02,2990.02 h60
  text "8" at 5661.16,2865.7 h60
  text "40.00mil (1.016mm)" at 5993.16,2865.7 h60
  text "PTH" at 6629.72,2865.7 h60
  text "Round" at 6888.86,2865.7 h60
  text "Top Layer - Bottom Layer" at 7264.02,2865.7 h60
  text "4" at 5661.16,2741.38 h60
  text "43.31mil (1.100mm)" at 5993.16,2741.38 h60
  text "PTH" at 6629.72,2741.38 h60
  text "Round" at 6888.86,2741.38 h60
  text "Top Layer - Bottom Layer" at 7264.02,2741.38 h60
  text "4" at 5661.16,2617.06 h60
  text "125.98mil (3.200mm)" at 5993.16,2617.06 h60
  text "PTH" at 6629.72,2617.06 h60
  text "Round" at 6888.86,2617.06 h60
  text "Top Layer - Bottom Layer" at 7264.02,2617.06 h60
  text "52 Total" at 5661.16,2492.74 h60
  text ".Layer_Name" at 577,-858.49 h60
M17 Embedded Cavity:
  text ".Layer_Name" at 577,-858.49 h60
M18 Embedded Assembly:
  text ".Layer_Name" at 577,-858.49 h60
M19 Embedded Keepout:
  text ".Layer_Name" at 577,-858.49 h60

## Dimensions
0,-400 to 1000,-400 on M2 Board Dimensions
0,0 to 0,2000 on M2 Board Dimensions
0,0 to 4300,0 on M2 Board Dimensions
